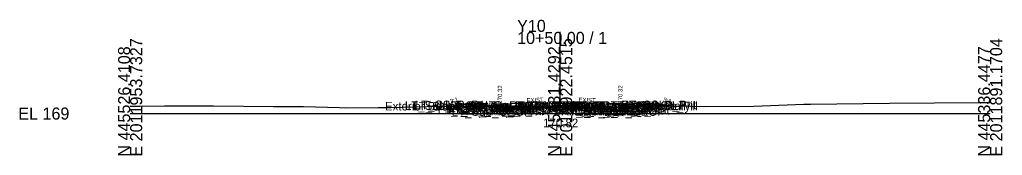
# Model space of a CAD drawing. Extents: x -26 to 203, y -10 to 3517.
# Drawn here: x -25.7 to 202.8, y 990.3 to 1021.8 of the extents above; entities that cross this region are included whole.
import ezdxf

# ---------------------------------------------------------------- set-up
doc = ezdxf.new("R2010")
doc.units = 0
for name, color, linetype in [('Default', 7, 'Continuous'), ('Exist CMT Pavement', 7, 'Continuous'), ('Exist Cross Section Cell', 7, 'Continuous'), ('Exist XS Center Line Elevation Label', 7, 'Continuous'), ('Exist XS Ground Line', 7, 'Continuous'), ('Prop CMT Conc Surface', 7, 'Continuous'), ('Prop CMT Concrete Structures', 7, 'Continuous'), ('Prop CMT Pvmt Course 1', 7, 'Continuous'), ('Prop CMT Pvmt Course 1 CG', 7, 'Continuous'), ('Prop CMT Pvmt Course 2', 7, 'Continuous'), ('Prop CMT Pvmt Course 3', 7, 'Continuous'), ('Prop CMT Pvmt Surface', 7, 'Continuous'), ('Prop CMT Pvmt Wedge Surface 1', 7, 'Continuous'), ('Prop CMT Pvmt Wedge Surface 2', 7, 'Continuous'), ('Prop CMT Pvmt Wedge Surface 3', 7, 'Continuous'), ('Prop CMT Slope Grass', 7, 'Continuous'), ('Prop CMT Subgrade Earthwork', 7, 'Continuous'), ('Prop XS Earthwork Shape', 7, 'Continuous'), ('Prop XS Hydro Elevations', 7, 'Continuous'), ('Prop XS SE Text', 7, 'Continuous'), ('Prop XS Side Slope Text', 7, 'Continuous'), ('Scratch_Level_0', 7, 'Continuous')]:
    doc.layers.add(name, color=color, linetype=linetype)

msp = doc.modelspace()

# ---------------------------------------------------------------- linework, layer by layer
at = {"layer": 'Exist CMT Pavement'}
for points in [[(100, 1001.82), (89.02, 1001.42), (89, 1001.42)], [(100, 1001.82), (100.04, 1001.82), (100.29, 1001.81), (111, 1001.47)]]:
    msp.add_lwpolyline(points, dxfattribs=at)
at = {"layer": 'Exist Cross Section Cell'}
for p, q in [((100, 1000), (100, 1018.95)), ((0, 1000), (100, 1000)), ((100, 1000), (200, 1000))]:
    msp.add_line(p, q, dxfattribs=at)
at = {"layer": 'Exist XS Ground Line'}
msp.add_lwpolyline([(0, 1001.72), (2.24, 1001.71), (8, 1001.78), (16.72, 1001.79), (18.08, 1001.78), (18.53, 1001.78), (19.42, 1001.76), (33.33, 1001.63), (40.34, 1001.64), (48.69, 1001.37), (50.12, 1001.35), (57.68, 1001.42), (60.65, 1001.42), (66.52, 1001.57), (71.57, 1001.72), (73.54, 1001.73), (74.18, 1001.72), (83.49, 1001.65), (86.46, 1001.62), (87.25, 1001.61), (88.63, 1001.4), (89.02, 1001.42), (100.04, 1001.82), (111.84, 1001.44), (112.76, 1001.58), (114.3, 1001.61), (126.78, 1001.79), (133.91, 1001.62), (145.02, 1001.69), (156.68, 1002.17), (157.85, 1002.17), (158.26, 1002.17), (176.58, 1002.42), (197.53, 1002.54), (200, 1002.54)], dxfattribs=at)
at = {"layer": 'Prop CMT Conc Surface'}
for points in [[(86, 1001.32), (86, 1001.82), (85.5, 1001.82)], [(88, 1001.46), (86, 1001.32)], [(112, 1001.46), (114, 1001.32)], [(114, 1001.32), (114, 1001.82), (114.5, 1001.82)]]:
    msp.add_lwpolyline(points, dxfattribs=at)
at = {"layer": 'Prop CMT Concrete Structures'}
for points in [[(88, 1001.46), (86, 1001.32), (86, 1001.82), (85.5, 1001.82)], [(85.5, 1001.82), (85.5, 1000.8), (88, 1000.87)], [(88, 1000.87), (88, 1001.46)], [(112, 1001.46), (114, 1001.32), (114, 1001.82), (114.5, 1001.82)], [(114.5, 1001.82), (114.5, 1000.8), (112, 1000.87)], [(112, 1000.87), (112, 1001.46)]]:
    msp.add_lwpolyline(points, dxfattribs=at)
at = {"layer": 'Prop CMT Pvmt Course 1'}
for points in [[(100, 1001.82), (88, 1001.46)], [(88, 1001.46), (88, 1001.21)], [(88, 1001.21), (89, 1001.24)], [(89, 1001.36), (100, 1001.69)], [(89, 1001.24), (89, 1001.36)], [(100, 1001.57), (100, 1001.82)], [(100, 1001.82), (112, 1001.46)], [(100, 1001.57), (100, 1001.82)], [(100, 1001.69), (100, 1001.57), (100, 1001.57)], [(111, 1001.36), (100, 1001.69)], [(100, 1001.69), (100, 1001.57), (100, 1001.57)], [(111, 1001.24), (111, 1001.36)], [(112, 1001.21), (111, 1001.24)], [(112, 1001.46), (112, 1001.21)]]:
    msp.add_lwpolyline(points, dxfattribs=at)
at = {"layer": 'Prop CMT Pvmt Course 1 CG'}
for points in [[(88, 1000.87), (85, 1000.78), (84.7, 1000.48)], [(84.7, 1000.48), (88, 1000.58)], [(88, 1000.58), (88, 1000.87)], [(112, 1000.87), (115, 1000.78), (115.3, 1000.48)], [(112, 1000.58), (112, 1000.87)], [(115.3, 1000.48), (112, 1000.58)]]:
    msp.add_lwpolyline(points, dxfattribs=at)
at = {"layer": 'Prop CMT Pvmt Course 2'}
for points in [[(89, 1001.24), (88, 1001.21)], [(88, 1001.21), (88, 1000.96)], [(88, 1000.96), (89, 1000.99)], [(89, 1000.99), (89, 1001.24)], [(111, 1000.99), (111, 1001.24)], [(111, 1001.24), (112, 1001.21)], [(112, 1000.96), (111, 1000.99)], [(112, 1001.21), (112, 1000.96)]]:
    msp.add_lwpolyline(points, dxfattribs=at)
at = {"layer": 'Prop CMT Pvmt Course 3'}
for points in [[(89, 1000.99), (88, 1000.96)], [(89, 1000.61), (89, 1000.99)], [(111, 1000.99), (112, 1000.96)], [(111, 1000.61), (111, 1000.99)], [(88, 1000.96), (88, 1000.58)], [(88, 1000.58), (89, 1000.61)], [(112, 1000.58), (111, 1000.61)], [(112, 1000.96), (112, 1000.58)]]:
    msp.add_lwpolyline(points, dxfattribs=at)
at = {"layer": 'Prop CMT Pvmt Surface'}
for points in [[(100, 1001.82), (88, 1001.46)], [(100, 1001.82), (112, 1001.46)]]:
    msp.add_lwpolyline(points, dxfattribs=at)
at = {"layer": 'Prop CMT Pvmt Wedge Surface 1'}
for points in [[(88, 1001.21), (88, 1001.46)], [(89, 1001.24), (88, 1001.21)], [(100, 1001.69), (89, 1001.36)], [(89, 1001.36), (89, 1001.24)], [(100, 1001.69), (111, 1001.36)], [(111, 1001.36), (111, 1001.24)], [(111, 1001.24), (112, 1001.21)], [(112, 1001.21), (112, 1001.46)]]:
    msp.add_lwpolyline(points, dxfattribs=at)
at = {"layer": 'Prop CMT Pvmt Wedge Surface 2'}
for points in [[(100, 1001.57), (88, 1001.21)], [(88, 1001.21), (88, 1001.46)], [(100, 1001.57), (112, 1001.21)], [(112, 1001.21), (112, 1001.46)]]:
    msp.add_lwpolyline(points, dxfattribs=at)
at = {"layer": 'Prop CMT Pvmt Wedge Surface 3'}
for points in [[(88, 1000.96), (88, 1001.46)], [(100, 1001.32), (88, 1000.96)], [(100, 1001.32), (112, 1000.96)], [(112, 1000.96), (112, 1001.46)]]:
    msp.add_lwpolyline(points, dxfattribs=at)
at = {"layer": 'Prop CMT Slope Grass'}
for points in [[(85.5, 1001.82), (76, 1002.01), (75.12, 1001.71)], [(114.5, 1001.82), (124, 1002.01), (124.74, 1001.76)]]:
    msp.add_lwpolyline(points, dxfattribs=at)
at = {"layer": 'Prop CMT Subgrade Earthwork'}
for points in [[(88, 1000.58), (84.7, 1000.48), (83.32, 1001.86)], [(89, 1000.61), (89.02, 1001.42)], [(111, 1000.61), (110.99, 1001.47)], [(112, 1000.58), (115.3, 1000.48), (116.68, 1001.86)], [(89, 1000.61), (88, 1000.58)], [(111, 1000.61), (112, 1000.58)]]:
    msp.add_lwpolyline(points, dxfattribs=at)
at = {"layer": 'Prop XS Earthwork Shape'}
for points in [[(83.53, 1001.65), (83.32, 1001.86), (76, 1002.01), (75.12, 1001.71), (83.49, 1001.65)], [(83.53, 1001.65), (85.5, 1001.63), (85.5, 1000.8), (88, 1000.87), (88, 1001.46), (88.24, 1001.46), (88.63, 1001.4), (89, 1001.42), (89.02, 1001.42), (89, 1000.61), (88, 1000.58), (84.7, 1000.48)], [(85.5, 1001.63), (86, 1001.62), (86, 1001.32), (88, 1001.46), (88, 1000.87), (85.5, 1000.8)], [(88.24, 1001.46), (88, 1001.46), (86, 1001.32), (86, 1001.62), (86.46, 1001.62), (87.25, 1001.61)], [(100.04, 1001.82), (100.29, 1001.81), (101.85, 1001.76), (100, 1001.82)], [(111.94, 1001.46), (112, 1001.46), (112, 1000.87), (114.5, 1000.8), (114.5, 1001.61), (116.46, 1001.64), (115.3, 1000.48), (112, 1000.58), (111, 1000.61), (110.99, 1001.47), (111, 1001.47), (111.84, 1001.44)], [(111.94, 1001.46), (112.76, 1001.58), (114, 1001.6), (114, 1001.32), (112, 1001.46)], [(114.3, 1001.61), (114.5, 1001.61), (114.5, 1000.8), (112, 1000.87), (112, 1001.46), (114, 1001.32), (114, 1001.6)], [(116.68, 1001.86), (124, 1002.01), (124.74, 1001.76), (116.46, 1001.64)]]:
    msp.add_lwpolyline(points, close=True, dxfattribs=at)

# ---------------------------------------------------------------- texts
at = {"layer": 'Default'}
msp.add_text('-', height=0.0001, dxfattribs=at).set_placement((0, 1000))
at = {"layer": 'Exist Cross Section Cell'}
for s, p in [('Y10', (90, 1018.95)), ('10+50.00 / 1', (90, 1016.15)), ('EL 169', (-26, 998.6))]:
    msp.add_text(s, height=2.8, dxfattribs=at).set_placement(p)
for s, p in [('E 2011953.7327', (2.8, 990)), ('E 2011922.4515', (102.8, 990)), ('E 2011891.1704', (202.8, 990)), ('N 445526.4108', (0, 990)), ('N 445431.4292', (100, 990)), ('N 445336.4477', (200, 990))]:
    msp.add_text(s, height=2.8, rotation=90, dxfattribs=at).set_placement(p)
at = {"layer": 'Exist XS Center Line Elevation Label'}
msp.add_text('170.82', height=2, dxfattribs=at).set_placement((96.03, 996.82))
at = {"layer": 'Prop XS Hydro Elevations'}
for p in [(86.5, 1002.32), (114.5, 1002.32)]:
    msp.add_text('170.32', height=1, rotation=90, dxfattribs=at).set_placement(p)
at = {"layer": 'Prop XS SE Text'}
for rotation, p in [(1.7184, (92.2, 1002.58)), (358.2816, (104.26, 1002.69))]:
    msp.add_text('EXIST.', height=1, rotation=rotation, dxfattribs=at).set_placement(p)
at = {"layer": 'Prop XS Side Slope Text'}
for rotation, p in [(18.4332, (74.57, 1002.32)), (341.5668, (123.86, 1002.84))]:
    msp.add_text('3:1', height=1, rotation=rotation, dxfattribs=at).set_placement(p)
at = {"layer": 'Scratch_Level_0'}
for s, p in [('Exterior Boundary', (59.26, 1000.71)), ('LT_Sub_Trench_Out_DLT', (63.89, 1000.86)), ('LT_Slope_Fill', (65.64, 1000.71)), ('LT_CSLP_Pnt', (66.17, 1001.01)), ('LT_CG1_Shelf_Out', (71.55, 999.78)), ('LT_CG_Top_Face', (73.26, 1000.82)), ('LT_CG_Top_BOC', (73.78, 1000.82)), ('LT_CG_Bot_BOC', (73.82, 999.8)), ('LT_PV_Sub_Tie_Out', (73.96, 1000.42)), ('LT_CG_Top_Gut', (74.24, 1000.32)), ('LT_Sub_OEOP', (74.81, 999.48)), ('LT_PV_OEEOP_EG', (76.54, 1000.42)), ('LT_CG_Bot_IE', (77.91, 999.87)), ('LT_Sub_OEOT', (78.08, 999.58)), ('LT_PV2_OEOT', (78.17, 1000.21)), ('LT_PV3_OEOT', (78.17, 999.96)), ('LT_Sub_OEEOP', (78.21, 999.61)), ('LT_PV2_OEEOP', (78.31, 1000.24)), ('LT_PV3_OEEOP', (78.31, 999.99)), ('LT_PV1_OEOT', (78.74, 1000.46)), ('LT_PV1_OEEOP', (78.87, 1000.36)), ('RT_PV_IEEOP_EG', (88.14, 1000.82)), ('LT_PV_IEEOP_EG', (88.19, 1000.82)), ('RT_PV2_IEEOP', (89.91, 1000.57)), ('RT_PV3_IEEOP', (89.91, 1000.32)), ('LT_PV2_IEEOP', (89.95, 1000.57)), ('LT_PV3_IEEOP', (89.95, 1000.32)), ('RT_PV1_IEEOP', (90.47, 1000.69)), ('LT_PV1_IEEOP', (90.52, 1000.69)), ('PV2_PGL', (93.91, 1000.57)), ('PV1_PGL', (94.47, 1000.82)), ('RT_PV_Sub_Tie_Out', (95.88, 1000.47)), ('RT_Sub_Trench_Out_DLT', (97.2, 1000.86)), ('RT_PV_OEEOP_EG', (98.5, 1000.47)), ('RT_Sub_OEEOP', (100.17, 999.61)), ('RT_PV2_OEEOP', (100.26, 1000.24)), ('RT_PV3_OEEOP', (100.26, 999.99)), ('RT_PV1_OEEOP', (100.83, 1000.36)), ('RT_CG_Top_Face', (101.21, 1000.82)), ('RT_CG1_Shelf_Out', (101.5, 999.78)), ('RT_CG_Bot_IE', (101.87, 999.87)), ('RT_Sub_OEOT', (102.03, 999.58)), ('RT_PV2_OEOT', (102.13, 1000.21)), ('RT_PV3_OEOT', (102.13, 999.96)), ('RT_CG_Top_Gut', (102.19, 1000.32)), ('RT_PV1_OEOT', (102.69, 1000.46)), ('RT_CG_Top_BOC', (102.74, 1000.82)), ('RT_CG_Bot_BOC', (102.77, 999.8)), ('RT_Sub_OEOP', (105.36, 999.48)), ('Exterior Boundary', (108.88, 1000.76)), ('RT_CSLP_Pnt', (114.13, 1001.01)), ('RT_Slope_Fill', (115.21, 1000.76))]:
    msp.add_text(s, height=2, dxfattribs=at).set_placement(p)

doc.saveas('drawing.dxf')
